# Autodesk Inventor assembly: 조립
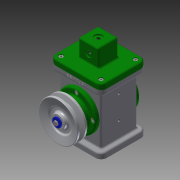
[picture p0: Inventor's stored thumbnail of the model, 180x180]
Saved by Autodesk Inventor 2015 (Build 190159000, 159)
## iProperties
Created: 2017-08
Part Number: 조립
Document SubType Name: Assembly
Designer: Administrator
Author: Administrator
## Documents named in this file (18)
- C:\Users\Administrator\Desktop\470807V1002\조립.iam
- C:\Users\Administrator\Desktop\470807V1002\답안본체.ipt
- C:\Users\Administrator\Desktop\470807V1002\E-링.ipt
- C:\Users\Administrator\Desktop\470807V1002\V-벨트풀리.ipt
- C:\Users\Administrator\Desktop\470807V1002\덮개.ipt
- C:\Users\Administrator\Desktop\470807V1002\뒤커버.ipt
- C:\Users\Administrator\Desktop\470807V1002\링크.ipt
- C:\Users\Administrator\Desktop\470807V1002\베어링 17 x 40 x 12.ipt
- C:\Users\Administrator\Desktop\470807V1002\볼트 M4 x 8.ipt
- C:\Users\Administrator\Desktop\470807V1002\볼트 M4 x 10.ipt
- C:\Users\Administrator\Desktop\470807V1002\슬라이더.ipt
- C:\Users\Administrator\Desktop\470807V1002\앞커버.ipt
- C:\Users\Administrator\Desktop\470807V1002\오일 실 17 30 8.ipt
- C:\Users\Administrator\Desktop\470807V1002\와셔 4x16.ipt
- C:\Users\Administrator\Desktop\470807V1002\클레비스 핀 6 x 22.ipt
- 클레비스 핀 6 x 22.ipt
- C:\Users\Administrator\Desktop\470807V1002\키 4 x 4 x 12.ipt
- C:\Users\Administrator\Desktop\470807V1002\편심축.ipt
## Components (2 placed, 2 different names)
1. E-링:1
2. V-벨트풀리:1
